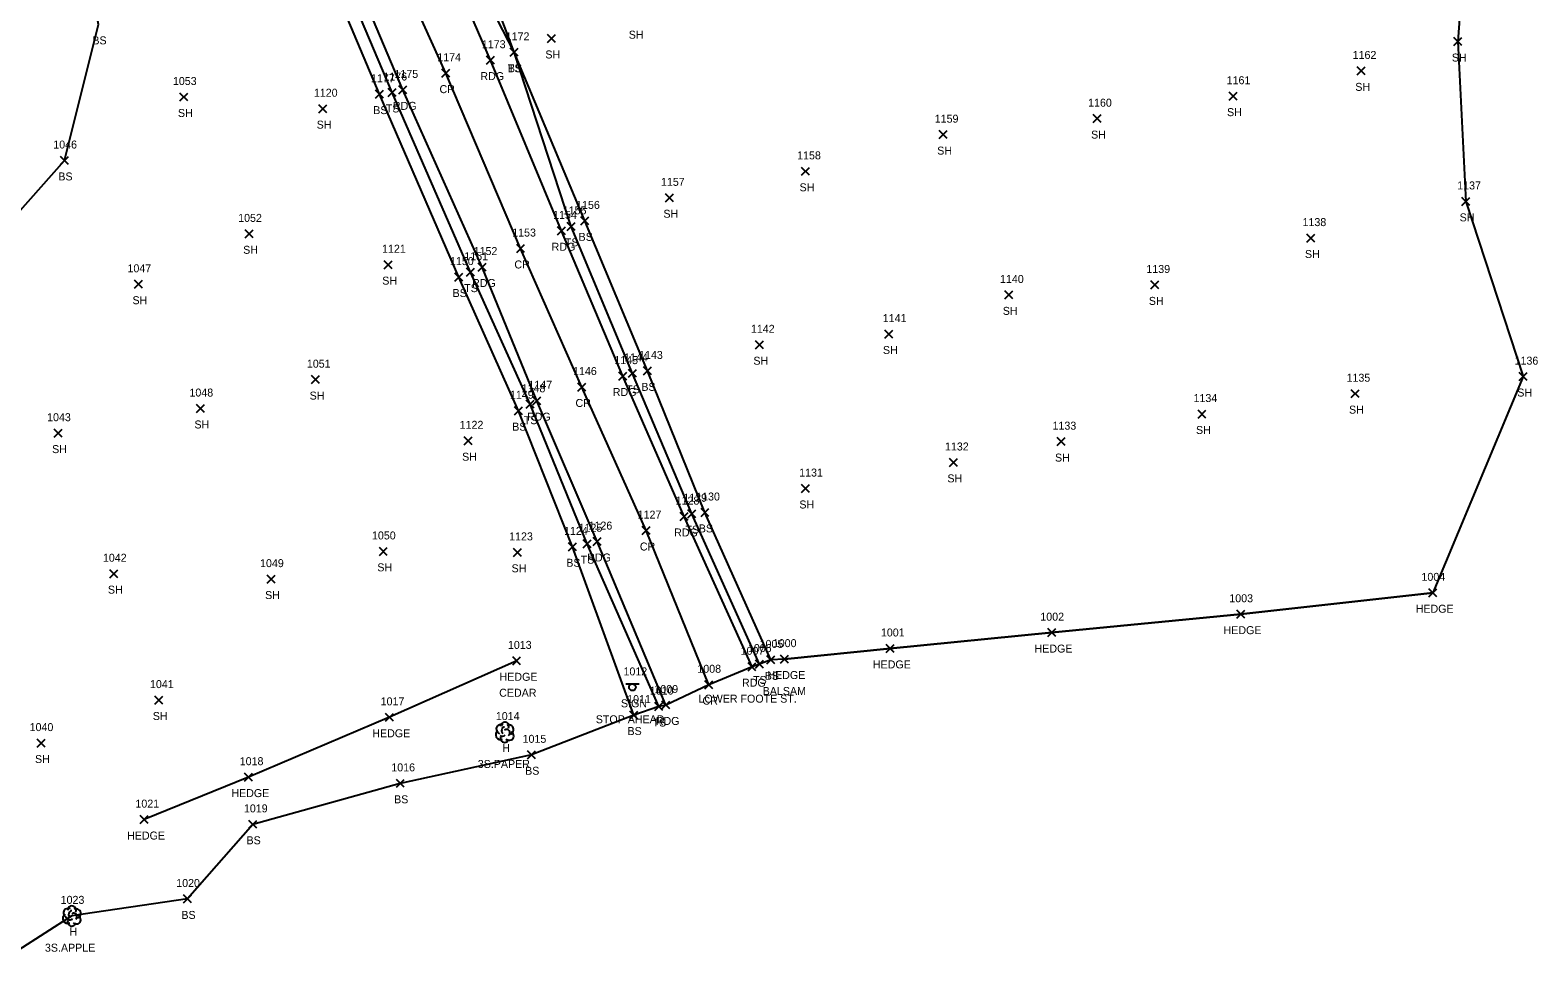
# Model space of a CAD drawing. Extents: x 1472233 to 1475777, y 540726 to 543442.
# Drawn here: x 1475319.7 to 1475697.8, y 542176 to 542407 of the extents above; entities that cross this region are included whole.
import ezdxf

# ---------------------------------------------------------------- set-up
doc = ezdxf.new("R2010")
doc.units = 0
for name, color, linetype in [('L_A', 7, 'Continuous'), ('L_C', 7, 'Continuous'), ('L_I', 7, 'Continuous'), ('L_TIC', 7, 'Continuous'), ('LAHR', 7, 'Continuous'), ('LELB', 7, 'Continuous'), ('LSOGP', 7, 'Continuous'), ('LTD', 7, 'Continuous'), ('P_A', 7, 'Continuous'), ('P_C', 7, 'Continuous'), ('P_I', 7, 'Continuous'), ('P_TIC', 7, 'Continuous'), ('PEU', 7, 'Continuous'), ('PRC', 7, 'Continuous'), ('S_A', 7, 'Continuous'), ('S_C', 7, 'Continuous'), ('S_I', 7, 'Continuous'), ('SSGN', 7, 'Continuous')]:
    doc.layers.add(name, color=color, linetype=linetype)

msp = doc.modelspace()

# ---------------------------------------------------------------- linework, layer by layer
at = {"layer": 'L_TIC'}
for points in [[(1475449.42, 542403.94), (1475451.42, 542405.94)], [(1475451.42, 542403.94), (1475449.42, 542405.94)], [(1475676.78, 542403.17), (1475678.78, 542405.17)], [(1475678.78, 542403.17), (1475676.78, 542405.17)], [(1475440.09, 542400.48), (1475442.09, 542402.48)], [(1475442.09, 542400.48), (1475440.09, 542402.48)], [(1475440.09, 542400.48), (1475442.09, 542402.48)], [(1475442.09, 542400.48), (1475440.09, 542402.48)], [(1475652.55, 542395.82), (1475654.55, 542397.82)], [(1475654.55, 542395.82), (1475652.55, 542397.82)], [(1475406.3, 542389.99), (1475408.3, 542391.99)], [(1475408.3, 542389.99), (1475406.3, 542391.99)], [(1475409.48, 542390.41), (1475411.48, 542392.41)], [(1475411.48, 542390.41), (1475409.48, 542392.41)], [(1475620.39, 542389.48), (1475622.39, 542391.48)], [(1475622.39, 542389.48), (1475620.39, 542391.48)], [(1475357.27, 542389.28), (1475359.27, 542391.28)], [(1475359.27, 542389.28), (1475357.27, 542391.28)], [(1475392.07, 542386.35), (1475394.07, 542388.35)], [(1475394.07, 542386.35), (1475392.07, 542388.35)], [(1475586.29, 542383.85), (1475588.29, 542385.85)], [(1475588.29, 542383.85), (1475586.29, 542385.85)], [(1475547.7, 542379.84), (1475549.7, 542381.84)], [(1475549.7, 542379.84), (1475547.7, 542381.84)], [(1475327.33, 542373.36), (1475329.33, 542375.36)], [(1475329.33, 542373.36), (1475327.33, 542375.36)], [(1475513.19, 542370.64), (1475515.19, 542372.64)], [(1475515.19, 542370.64), (1475513.19, 542372.64)], [(1475479.03, 542364.01), (1475481.03, 542366.01)], [(1475481.03, 542364.01), (1475479.03, 542366.01)], [(1475678.73, 542363.1), (1475680.73, 542365.1)], [(1475680.73, 542363.1), (1475678.73, 542365.1)], [(1475454.39, 542356.85), (1475456.39, 542358.85)], [(1475456.39, 542356.85), (1475454.39, 542358.85)], [(1475457.81, 542358.22), (1475459.81, 542360.22)], [(1475459.81, 542358.22), (1475457.81, 542360.22)], [(1475373.64, 542354.97), (1475375.64, 542356.97)], [(1475375.64, 542354.97), (1475373.64, 542356.97)], [(1475639.93, 542353.91), (1475641.93, 542355.91)], [(1475641.93, 542353.91), (1475639.93, 542355.91)], [(1475408.52, 542347.24), (1475410.52, 542349.24)], [(1475410.52, 542347.24), (1475408.52, 542349.24)], [(1475426.2, 542344.14), (1475428.2, 542346.14)], [(1475428.2, 542344.14), (1475426.2, 542346.14)], [(1475429.15, 542345.36), (1475431.15, 542347.36)], [(1475431.15, 542345.36), (1475429.15, 542347.36)], [(1475345.88, 542342.33), (1475347.88, 542344.33)], [(1475347.88, 542342.33), (1475345.88, 542344.33)], [(1475600.79, 542342.16), (1475602.79, 542344.16)], [(1475602.79, 542342.16), (1475600.79, 542344.16)], [(1475564.15, 542339.66), (1475566.15, 542341.66)], [(1475566.15, 542339.66), (1475564.15, 542341.66)], [(1475534.09, 542329.84), (1475536.09, 542331.84)], [(1475536.09, 542329.84), (1475534.09, 542331.84)], [(1475501.59, 542327.16), (1475503.59, 542329.16)], [(1475503.59, 542327.16), (1475501.59, 542329.16)], [(1475390.3, 542318.42), (1475392.3, 542320.42)], [(1475392.3, 542318.42), (1475390.3, 542320.42)], [(1475469.79, 542320), (1475471.79, 542322)], [(1475471.79, 542320), (1475469.79, 542322)], [(1475473.54, 542320.61), (1475475.54, 542322.61)], [(1475475.54, 542320.61), (1475473.54, 542322.61)], [(1475693.18, 542319.18), (1475695.18, 542321.18)], [(1475695.18, 542319.18), (1475693.18, 542321.18)], [(1475650.98, 542314.9), (1475652.98, 542316.9)], [(1475652.98, 542314.9), (1475650.98, 542316.9)], [(1475361.42, 542311.18), (1475363.42, 542313.18)], [(1475363.42, 542311.18), (1475361.42, 542313.18)], [(1475441.16, 542310.63), (1475443.16, 542312.63)], [(1475443.16, 542310.63), (1475441.16, 542312.63)], [(1475444.09, 542312.25), (1475446.09, 542314.25)], [(1475446.09, 542312.25), (1475444.09, 542314.25)], [(1475612.6, 542309.8), (1475614.6, 542311.8)], [(1475614.6, 542309.8), (1475612.6, 542311.8)], [(1475325.73, 542305), (1475327.73, 542307)], [(1475327.73, 542305), (1475325.73, 542307)], [(1475428.55, 542303.09), (1475430.55, 542305.09)], [(1475430.55, 542303.09), (1475428.55, 542305.09)], [(1475577.24, 542302.88), (1475579.24, 542304.88)], [(1475579.24, 542302.88), (1475577.24, 542304.88)], [(1475550.25, 542297.66), (1475552.25, 542299.66)], [(1475552.25, 542297.66), (1475550.25, 542299.66)], [(1475513.12, 542291.12), (1475515.12, 542293.12)], [(1475515.12, 542291.12), (1475513.12, 542293.12)], [(1475484.64, 542284.8), (1475486.64, 542286.8)], [(1475486.64, 542284.8), (1475484.64, 542286.8)], [(1475487.95, 542285.12), (1475489.95, 542287.12)], [(1475489.95, 542285.12), (1475487.95, 542287.12)], [(1475454.73, 542276.51), (1475456.73, 542278.51)], [(1475456.73, 542276.51), (1475454.73, 542278.51)], [(1475458.38, 542277.29), (1475460.38, 542279.29)], [(1475460.38, 542277.29), (1475458.38, 542279.29)], [(1475407.28, 542275.36), (1475409.28, 542277.36)], [(1475409.28, 542275.36), (1475407.28, 542277.36)], [(1475440.96, 542275.12), (1475442.96, 542277.12)], [(1475442.96, 542275.12), (1475440.96, 542277.12)], [(1475339.71, 542269.77), (1475341.71, 542271.77)], [(1475341.71, 542269.77), (1475339.71, 542271.77)], [(1475379.14, 542268.41), (1475381.14, 542270.41)], [(1475381.14, 542268.41), (1475379.14, 542270.41)], [(1475670.49, 542264.98), (1475672.49, 542266.98)], [(1475672.49, 542264.98), (1475670.49, 542266.98)], [(1475622.3, 542259.61), (1475624.3, 542261.61)], [(1475624.3, 542259.61), (1475622.3, 542261.61)], [(1475574.9, 542254.99), (1475576.9, 542256.99)], [(1475576.9, 542254.99), (1475574.9, 542256.99)], [(1475534.36, 542251.03), (1475536.36, 542253.03)], [(1475536.36, 542251.03), (1475534.36, 542253.03)], [(1475440.72, 542247.92), (1475442.72, 542249.92)], [(1475442.72, 542247.92), (1475440.72, 542249.92)], [(1475501.6, 542247.12), (1475503.6, 542249.12)], [(1475503.6, 542247.12), (1475501.6, 542249.12)], [(1475504.49, 542248.16), (1475506.49, 542250.16)], [(1475506.49, 542248.16), (1475504.49, 542250.16)], [(1475507.9, 542248.36), (1475509.9, 542250.36)], [(1475509.9, 542248.36), (1475507.9, 542250.36)], [(1475350.97, 542238.09), (1475352.97, 542240.09)], [(1475352.97, 542238.09), (1475350.97, 542240.09)], [(1475470.07, 542234.32), (1475472.07, 542236.32)], [(1475472.07, 542234.32), (1475470.07, 542236.32)], [(1475470.07, 542234.32), (1475472.07, 542236.32)], [(1475472.07, 542234.32), (1475470.07, 542236.32)], [(1475476.4, 542236.46), (1475478.4, 542238.46)], [(1475478.4, 542236.46), (1475476.4, 542238.46)], [(1475408.81, 542233.76), (1475410.81, 542235.76)], [(1475410.81, 542233.76), (1475408.81, 542235.76)], [(1475321.43, 542227.31), (1475323.43, 542229.31)], [(1475323.43, 542227.31), (1475321.43, 542229.31)], [(1475444.4, 542224.37), (1475446.4, 542226.37)], [(1475446.4, 542224.37), (1475444.4, 542226.37)], [(1475373.46, 542218.76), (1475375.46, 542220.76)], [(1475375.46, 542218.76), (1475373.46, 542220.76)], [(1475411.54, 542217.21), (1475413.54, 542219.21)], [(1475413.54, 542217.21), (1475411.54, 542219.21)], [(1475347.31, 542208.12), (1475349.31, 542210.12)], [(1475349.31, 542208.12), (1475347.31, 542210.12)], [(1475374.52, 542206.93), (1475376.52, 542208.93)], [(1475376.52, 542206.93), (1475374.52, 542208.93)], [(1475358.19, 542188.22), (1475360.19, 542190.22)], [(1475360.19, 542188.22), (1475358.19, 542190.22)]]:
    msp.add_lwpolyline(points, dxfattribs=at)
at = {"layer": 'LAHR'}
for points in [[(1475508.9, 542249.36), (1475535.36, 542252.03), (1475575.9, 542255.99), (1475623.3, 542260.61), (1475671.49, 542265.98)], [(1475441.72, 542248.92), (1475409.81, 542234.76), (1475374.46, 542219.76), (1475348.31, 542209.12)]]:
    msp.add_lwpolyline(points, dxfattribs=at)
at = {"layer": 'LELB'}
for points in [[(1475505.49, 542249.16), (1475488.95, 542286.12), (1475474.54, 542321.61), (1475458.81, 542359.22), (1475441.09, 542401.48), (1475421.08, 542440.37), (1475396.03, 542499.2), (1475376.68, 542551.62), (1475357.79, 542598.07), (1475337.62, 542645.37)], [(1475502.6, 542248.12), (1475485.64, 542285.8), (1475470.79, 542321), (1475455.39, 542357.85), (1475441.09, 542401.48), (1475426.05, 542441.52), (1475400.33, 542500.31), (1475376.68, 542551.62), (1475354.38, 542596.74), (1475334.54, 542644.47)], [(1475471.07, 542235.32), (1475455.73, 542277.51), (1475442.16, 542311.63), (1475427.2, 542345.14), (1475407.3, 542390.99), (1475390.5, 542430.83), (1475365.35, 542490.83), (1475345.68, 542538.17), (1475324.25, 542586.46), (1475305.93, 542636.69)], [(1475477.4, 542237.46), (1475459.38, 542278.29), (1475445.09, 542313.25), (1475430.15, 542346.36), (1475410.48, 542391.41), (1475393.47, 542431.66), (1475368.2, 542491.05), (1475347.92, 542539.36), (1475326.62, 542587.53), (1475308.04, 542636.9)], [(1475200.77, 542308.82), (1475241.78, 542316.68), (1475274.04, 542320.33), (1475301.6, 542344.24), (1475328.33, 542374.36), (1475336.87, 542408.47), (1475330.86, 542442.76), (1475311.21, 542502.26), (1475281.99, 542519.93), (1475248.21, 542520.89), (1475204.7, 542516.83), (1475158.55, 542517), (1475106, 542512.66), (1475101.78, 542479.34), (1475121.91, 542432.37), (1475141.93, 542394.7), (1475161.94, 542358.5), (1475181.79, 542323.33), (1475176.76, 542299.8)], [(1475471.07, 542235.32), (1475445.4, 542225.37), (1475412.54, 542218.21), (1475375.52, 542207.93), (1475359.19, 542189.22)]]:
    msp.add_lwpolyline(points, dxfattribs=at)
at = {"layer": 'LSOGP'}
msp.add_lwpolyline([(1475684.8, 542500.39), (1475677.78, 542404.17), (1475679.73, 542364.1), (1475694.18, 542320.18), (1475671.49, 542265.98), (1475623.3, 542260.61), (1475575.9, 542255.99), (1475535.36, 542252.03), (1475508.9, 542249.36), (1475505.49, 542249.16), (1475502.6, 542248.12), (1475500.74, 542247.44), (1475489.88, 542242.93), (1475479.12, 542237.85), (1475477.4, 542237.46), (1475471.07, 542235.32), (1475445.4, 542225.37), (1475412.54, 542218.21), (1475375.52, 542207.93), (1475359.19, 542189.22), (1475330.12, 542185), (1475316.58, 542176.31)], dxfattribs=at)
at = {"layer": 'LTD'}
for p, q in [((1475438.69, 542231.07), (1475438.69, 542231.07)), ((1475438.69, 542231.07), (1475438.69, 542231.07)), ((1475330.12, 542185), (1475330.12, 542185)), ((1475330.12, 542185), (1475330.12, 542185))]:
    msp.add_line(p, q, dxfattribs=at)
for centre in [(1475438.74, 542232.51), (1475330.17, 542186.43)]:
    msp.add_arc(centre, 1.05, 335.5272, 180.9563, dxfattribs=at)
for centre, major_axis, ratio, start_param, end_param in [((1475437.9, 542231.74), (1.21, -0.51), 0.895232, 1.570796, 4.712389), ((1475439.73, 542231.66), (-1.14, -0.48), 0.949671, 1.570796, 4.712389), ((1475437.61, 542230.36), (0.58, -1.04), 0.959034, 3.141593, 6.283185), ((1475438.69, 542229.57), (0.26, 1.06), 0.942809, 1.570796, 4.712389), ((1475438.23, 542230.32), (-0.625, -0.083), 0.423636, 0, 3.141593), ((1475438.48, 542231.53), (-0.208, -0.792), 0.645439, 3.141593, 6.283185), ((1475439.19, 542230.91), (-0.5, 0.667), 0.989748, 3.141593, 6.283185), ((1475439.69, 542230.24), (-1.09, 0.79), 0.841452, 1.570796, 4.712389), ((1475329.04, 542184.29), (0.58, -1.04), 0.959034, 3.141593, 6.283185), ((1475329.33, 542185.66), (1.21, -0.51), 0.895232, 1.570796, 4.712389), ((1475330.12, 542183.5), (0.26, 1.06), 0.942809, 1.570796, 4.712389), ((1475329.66, 542184.25), (-0.625, -0.083), 0.423636, 0, 3.141593), ((1475329.91, 542185.45), (-0.208, -0.792), 0.645439, 3.141593, 6.283185), ((1475330.62, 542184.83), (-0.5, 0.667), 0.989748, 3.141593, 6.283185), ((1475331.12, 542184.16), (-1.09, 0.79), 0.841452, 1.570796, 4.712389), ((1475331.16, 542185.58), (-1.14, -0.48), 0.949671, 1.570796, 4.712389)]:
    msp.add_ellipse(centre, major_axis=major_axis, ratio=ratio, start_param=start_param, end_param=end_param, dxfattribs=at)
at = {"layer": 'P_TIC'}
for points in [[(1475434.12, 542398.51), (1475436.12, 542400.51)], [(1475436.12, 542398.51), (1475434.12, 542400.51)], [(1475422.94, 542395.25), (1475424.94, 542397.25)], [(1475424.94, 542395.25), (1475422.94, 542397.25)], [(1475412.19, 542391.06), (1475414.19, 542393.06)], [(1475414.19, 542391.06), (1475412.19, 542393.06)], [(1475451.99, 542355.73), (1475453.99, 542357.73)], [(1475453.99, 542355.73), (1475451.99, 542357.73)], [(1475441.72, 542351.29), (1475443.72, 542353.29)], [(1475443.72, 542351.29), (1475441.72, 542353.29)], [(1475432.04, 542346.65), (1475434.04, 542348.65)], [(1475434.04, 542346.65), (1475432.04, 542348.65)], [(1475467.33, 542319.31), (1475469.33, 542321.31)], [(1475469.33, 542319.31), (1475467.33, 542321.31)], [(1475457.04, 542316.57), (1475459.04, 542318.57)], [(1475459.04, 542316.57), (1475457.04, 542318.57)], [(1475445.81, 542313.13), (1475447.81, 542315.13)], [(1475447.81, 542313.13), (1475445.81, 542315.13)], [(1475482.72, 542284.1), (1475484.72, 542286.1)], [(1475484.72, 542284.1), (1475482.72, 542286.1)], [(1475473.18, 542280.58), (1475475.18, 542282.58)], [(1475475.18, 542280.58), (1475473.18, 542282.58)], [(1475460.93, 542277.83), (1475462.93, 542279.83)], [(1475462.93, 542277.83), (1475460.93, 542279.83)], [(1475499.74, 542246.44), (1475501.74, 542248.44)], [(1475501.74, 542246.44), (1475499.74, 542248.44)], [(1475488.88, 542241.93), (1475490.88, 542243.93)], [(1475490.88, 542241.93), (1475488.88, 542243.93)], [(1475478.12, 542236.85), (1475480.12, 542238.85)], [(1475480.12, 542236.85), (1475478.12, 542238.85)]]:
    msp.add_lwpolyline(points, dxfattribs=at)
at = {"layer": 'PEU'}
for points in [[(1475500.74, 542247.44), (1475483.72, 542285.1), (1475468.33, 542320.31), (1475452.99, 542356.73), (1475435.12, 542399.51), (1475417.65, 542439.86), (1475393.18, 542498.17), (1475371.46, 542549.57), (1475352.22, 542595.99), (1475331.5, 542643.66), (1475314.88, 542685.29), (1475295.94, 542731.34), (1475280.16, 542772.22), (1475258.36, 542823.21), (1475241.93, 542862.67), (1475217.41, 542918.69), (1475198.88, 542961.72), (1475177.58, 543009.96), (1475156.54, 543059.07), (1475132.79, 543115.63), (1475115.44, 543155.27)], [(1475479.12, 542237.85), (1475461.93, 542278.83), (1475446.81, 542314.13), (1475433.04, 542347.65), (1475413.19, 542392.06), (1475396.09, 542432.46), (1475370.67, 542491.66), (1475350.46, 542540.4), (1475329.23, 542588.78), (1475309.74, 542637.56), (1475293.45, 542677.97), (1475275.03, 542722.66), (1475253.25, 542774.01), (1475237.56, 542813.36), (1475220.2, 542854.42), (1475196.99, 542908.72), (1475177.68, 542952.09), (1475158.12, 543000.84), (1475137.1, 543050.15), (1475113.34, 543107.63), (1475097.32, 543147.51)]]:
    msp.add_lwpolyline(points, dxfattribs=at)
at = {"layer": 'PRC'}
msp.add_lwpolyline([(1475489.88, 542242.93), (1475474.18, 542281.58), (1475458.04, 542317.57), (1475442.72, 542352.29), (1475423.94, 542396.25), (1475405.97, 542436.05), (1475382.11, 542495.26), (1475360.38, 542544.97), (1475340.99, 542592.55), (1475321.95, 542640.5)], dxfattribs=at)
at = {"layer": 'SSGN'}
for p, q in [((1475469.08, 542243.13), (1475472.42, 542243.13)), ((1475470.73, 542242.29), (1475470.73, 542242.29))]:
    msp.add_line(p, q, dxfattribs=at)
msp.add_circle((1475470.73, 542242.29), 0.833, dxfattribs=at)

# ---------------------------------------------------------------- texts
at = {"layer": 'L_A'}
for s, p in [('SH', (1475469.83, 542404.9)), ('BS', (1475335.31, 542403.47)), ('SH', (1475448.91, 542399.94)), ('SH', (1475676.26, 542399.17)), ('TS', (1475439.5, 542396.48)), ('BS', (1475439.53, 542396.48)), ('SH', (1475652.04, 542391.82)), ('BS', (1475405.74, 542385.99)), ('TS', (1475408.89, 542386.41)), ('SH', (1475356.76, 542385.28)), ('SH', (1475391.56, 542382.35)), ('SH', (1475619.88, 542385.48)), ('SH', (1475585.78, 542379.85)), ('SH', (1475547.19, 542375.84)), ('BS', (1475326.77, 542369.36)), ('SH', (1475512.67, 542366.64)), ('SH', (1475478.52, 542360.01)), ('SH', (1475678.21, 542359.1)), ('TS', (1475453.8, 542352.85)), ('BS', (1475457.25, 542354.22)), ('SH', (1475373.13, 542350.97)), ('SH', (1475639.42, 542349.91)), ('SH', (1475408.01, 542343.24)), ('BS', (1475425.64, 542340.14)), ('TS', (1475428.56, 542341.36)), ('SH', (1475345.37, 542338.33)), ('SH', (1475600.27, 542338.16)), ('SH', (1475563.64, 542335.66)), ('SH', (1475533.58, 542325.84)), ('SH', (1475501.08, 542323.16)), ('SH', (1475389.79, 542314.42)), ('TS', (1475469.19, 542316)), ('BS', (1475472.99, 542316.61)), ('SH', (1475692.66, 542315.18)), ('SH', (1475650.47, 542310.9)), ('SH', (1475360.91, 542307.18)), ('BS', (1475440.6, 542306.63)), ('TS', (1475443.5, 542308.25)), ('SH', (1475612.09, 542305.8)), ('SH', (1475325.21, 542301)), ('SH', (1475428.04, 542299.09)), ('SH', (1475576.73, 542298.88)), ('SH', (1475549.74, 542293.66)), ('SH', (1475512.61, 542287.12)), ('TS', (1475484.05, 542280.8)), ('BS', (1475487.39, 542281.12)), ('BS', (1475454.17, 542272.51)), ('TS', (1475457.78, 542273.29)), ('SH', (1475406.77, 542271.36)), ('SH', (1475440.44, 542271.12)), ('SH', (1475339.2, 542265.77)), ('SH', (1475378.63, 542264.41)), ('HEDGE', (1475667.19, 542260.98)), ('HEDGE', (1475619, 542255.61)), ('HEDGE', (1475571.6, 542250.99)), ('HEDGE', (1475531.06, 542247.03)), ('HEDGE', (1475437.42, 542243.92)), ('TS', (1475501.01, 542243.12)), ('BS', (1475503.93, 542244.16)), ('HEDGE', (1475504.6, 542244.36)), ('SH', (1475350.46, 542234.09)), ('TS', (1475475.81, 542232.46)), ('HEDGE', (1475405.51, 542229.76)), ('BS', (1475469.51, 542230.32)), ('BS', (1475469.51, 542230.32)), ('SH', (1475320.92, 542223.31)), ('H', (1475438.12, 542226.07)), ('BS', (1475443.84, 542220.37)), ('HEDGE', (1475370.16, 542214.76)), ('BS', (1475410.98, 542213.21)), ('HEDGE', (1475344.01, 542204.12)), ('BS', (1475373.96, 542202.93)), ('BS', (1475357.63, 542184.22)), ('H', (1475329.55, 542180))]:
    msp.add_text(s, height=2, dxfattribs=at).set_placement(p)
at = {"layer": 'L_C'}
for s, p in [('CEDAR', (1475437.33, 542239.92)), ('BALSAM', (1475503.42, 542240.36)), ('3S.PAPER', (1475431.97, 542222.07)), ('3S.APPLE', (1475323.41, 542176))]:
    msp.add_text(s, height=2, dxfattribs=at).set_placement(p)
at = {"layer": 'L_I'}
for s, p in [('1172', (1475438.97, 542404.48)), ('1172', (1475438.97, 542404.48)), ('1162', (1475651.38, 542399.82)), ('1053', (1475355.5, 542393.28)), ('1177', (1475405.18, 542393.99)), ('1176', (1475408.3, 542394.41)), ('1161', (1475619.78, 542393.48)), ('1120', (1475390.86, 542390.35)), ('1160', (1475585.03, 542387.85)), ('1159', (1475546.57, 542383.84)), ('1046', (1475325.5, 542377.36)), ('1158', (1475512.06, 542374.64)), ('1157', (1475477.91, 542368.01)), ('1137', (1475677.6, 542367.1)), ('1155', (1475453.27, 542360.85)), ('1156', (1475456.63, 542362.22)), ('1052', (1475371.87, 542358.97)), ('1138', (1475638.81, 542357.91)), ('1121', (1475407.96, 542351.24)), ('1150', (1475424.99, 542348.14)), ('1151', (1475428.59, 542349.36)), ('1047', (1475344.11, 542346.33)), ('1139', (1475599.65, 542346.16)), ('1140', (1475562.94, 542343.66)), ('1141', (1475533.53, 542333.84)), ('1142', (1475500.46, 542331.16)), ('1051', (1475389.1, 542322.42)), ('1144', (1475468.66, 542324)), ('1143', (1475472.42, 542324.61)), ('1136', (1475691.99, 542323.18)), ('1135', (1475649.85, 542318.9)), ('1048', (1475359.65, 542315.18)), ('1149', (1475440.03, 542314.63)), ('1148', (1475442.96, 542316.25)), ('1134', (1475611.47, 542313.8)), ('1043', (1475323.95, 542309)), ('1122', (1475427.42, 542307.09)), ('1133', (1475576.11, 542306.88)), ('1132', (1475549.13, 542301.66)), ('1131', (1475512.57, 542295.12)), ('1129', (1475483.51, 542288.8)), ('1130', (1475486.74, 542289.12)), ('1124', (1475453.6, 542280.51)), ('1125', (1475457.25, 542281.29)), ('1050', (1475405.43, 542279.36)), ('1123', (1475439.83, 542279.12)), ('1042', (1475337.94, 542273.77)), ('1049', (1475377.36, 542272.41)), ('1004', (1475668.64, 542268.98)), ('1003', (1475620.45, 542263.61)), ('1002', (1475573.05, 542258.99)), ('1001', (1475533.07, 542255.03)), ('1013', (1475439.52, 542251.92)), ('1006', (1475499.7, 542251.12)), ('1005', (1475502.64, 542252.16)), ('1000', (1475505.96, 542252.36)), ('1041', (1475349.76, 542242.09)), ('1011', (1475469.43, 542238.32)), ('1011', (1475469.43, 542238.32)), ('1010', (1475475.11, 542240.46)), ('1017', (1475407.61, 542237.76)), ('1040', (1475319.57, 542231.31)), ('1014', (1475436.49, 542234.07)), ('1015', (1475443.2, 542228.37)), ('1018', (1475372.26, 542222.76)), ('1016', (1475410.28, 542221.21)), ('1021', (1475346.1, 542212.12)), ('1019', (1475373.31, 542210.93)), ('1020', (1475356.33, 542192.22)), ('1023', (1475327.35, 542188))]:
    msp.add_text(s, height=2, dxfattribs=at).set_placement(p)
at = {"layer": 'P_A'}
for s, p in [('RDG', (1475432.61, 542394.51)), ('CR', (1475422.37, 542391.25)), ('RDG', (1475410.68, 542387.06)), ('RDG', (1475450.48, 542351.73)), ('CR', (1475441.15, 542347.29)), ('RDG', (1475430.53, 542342.65)), ('RDG', (1475465.82, 542315.31)), ('CR', (1475456.47, 542312.57)), ('RDG', (1475444.3, 542309.13)), ('RDG', (1475481.21, 542280.1)), ('CR', (1475472.62, 542276.58)), ('RDG', (1475459.42, 542273.83)), ('RDG', (1475498.23, 542242.44)), ('CR', (1475488.32, 542237.93)), ('RDG', (1475476.61, 542232.85))]:
    msp.add_text(s, height=2, dxfattribs=at).set_placement(p)
at = {"layer": 'P_C'}
msp.add_text('LOWER FOOTE ST.', height=2, dxfattribs=at).set_placement((1475487.31, 542238.44))
at = {"layer": 'P_I'}
for s, p in [('1173', (1475432.99, 542402.51)), ('1174', (1475421.81, 542399.25)), ('1175', (1475411.07, 542395.06)), ('1154', (1475450.86, 542359.73)), ('1153', (1475440.6, 542355.29)), ('1152', (1475430.92, 542350.65)), ('1145', (1475466.2, 542323.31)), ('1146', (1475455.86, 542320.57)), ('1147', (1475444.68, 542317.13)), ('1128', (1475481.59, 542288.1)), ('1127', (1475472.06, 542284.58)), ('1126', (1475459.75, 542281.83)), ('1007', (1475497.89, 542250.44)), ('1008', (1475487.03, 542245.93)), ('1009', (1475476.26, 542240.85))]:
    msp.add_text(s, height=2, dxfattribs=at).set_placement(p)
at = {"layer": 'S_A'}
msp.add_text('SIGN', height=2, dxfattribs=at).set_placement((1475467.87, 542237.27))
at = {"layer": 'S_C'}
msp.add_text('STOP AHEAD', height=2, dxfattribs=at).set_placement((1475461.55, 542233.27))
at = {"layer": 'S_I'}
msp.add_text('1012', height=2, dxfattribs=at).set_placement((1475468.51, 542245.27))

doc.saveas('drawing.dxf')
